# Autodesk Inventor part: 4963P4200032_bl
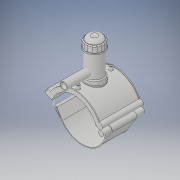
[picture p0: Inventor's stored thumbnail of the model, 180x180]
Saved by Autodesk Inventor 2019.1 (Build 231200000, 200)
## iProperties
Created: 2017-07
Part Number: 4963P4200032_bl
Material: Generic
Document SubType Name: Modeling
Designer: KIM
Density: 1 g/cm^3
Appearance: Default
Author: KIM
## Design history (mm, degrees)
derived "4963P4.ipt"
feature "Solid1::4963P4.ipt" dims "ScaleForDerivedMember" = 10
feature "Solid2::4963P4.ipt" dims "ScaleForDerivedMember" = 10
feature "Solid3::4963P4.ipt" dims "ScaleForDerivedMember" = 10
tag "TaggingFeature1"
body "Solid1"
body "Solid2"
body "Solid3"
other parameters: "d2" = 262.6 [user parameter], "d4" = 176 [user parameter], "d5" = 0 [user parameter], "d6" = 0.1 [user parameter], "d8" = 0 [user parameter], "d19" = 6 [user parameter], "d20" = 6 [user parameter], "d21" = 105.6 [user parameter], "d23" = 0 [user parameter], "d24" = 52.8 [user parameter], "d26" = 0 [user parameter], "d27" = 3 [user parameter], "d28" = 3 [user parameter], "d29" = 3 [user parameter], "d30" = 66.66667 [user parameter], "d31" = 6 [user parameter], "d32" = 0 [user parameter], "d33" = 0 [user parameter], "d34" = 0.6 [user parameter], "d40" = 120.64 [user parameter], "d43" = 0 [user parameter], "d45" = 0 [user parameter], "d47" = 221.6 [user parameter], "d70" = 15 [user parameter], "d72" = 0 [user parameter], "d73" = 6 [user parameter], "d75" = 5 [user parameter], "d76" = 0 [user parameter], "d79" = 15 [user parameter], "d80" = 70.4 [user parameter], "d82" = 5 deg [user parameter], "d84" = 4 [user parameter], "d85" = 14 [user parameter], "d86" = 0 [user parameter], "d87" = 3 [user parameter], "d88" = 0 [user parameter], "d89" = 1 [user parameter], "d90" = 1 [user parameter], "d91" = 140.8 [user parameter], "d92" = 0 [user parameter], "d93" = 0.5 [user parameter], "d94" = 105.26316 [user parameter], "d96" = 236.64 [user parameter], "d97" = 3.52 [user parameter], "d98" = 0 [user parameter], "d102" = 2 [user parameter], "d120" = 140 deg [user parameter], "d121" = 24.228 [user parameter], "d122" = 20 deg [user parameter], "d123" = 464 [user parameter], "d124" = 139.2 [user parameter], "d126" = 0 [user parameter], "d143" = 206 [user parameter], "d145" = 24.61538 [user parameter], "d149" = 3 [user parameter], "d150" = 27.07692 [user parameter], "d153" = 176 [user parameter], "d154" = 0 [user parameter], "d156" = 116 [user parameter], "d157" = 160 deg [user parameter], "d159" = 6.4 [user parameter], "d161" = 3 [user parameter], "d162" = 105.6 [user parameter], "d163" = 0 [user parameter], "d168" = 113.17073 [user parameter], "d170" = 3 [user parameter], "d172" = 0 [user parameter], "d173" = 1 [user parameter], "d176" = 20 deg [user parameter], "d177" = 14 [user parameter], "d178" = 32 [user parameter], "d180" = 0 [user parameter], "d183" = 12.8 [user parameter], "d184" = 11.2 [user parameter], "d185" = 57.2 [user parameter], "d186" = 57.2 [user parameter], "d187" = 116 [user parameter], "d188" = 9.6 [user parameter], "d189" = 14 [user parameter], "d190" = 0 [user parameter], "d191" = 174 [user parameter], "d193" = 6.4 [user parameter], "d194" = 6.16 [user parameter], "d195" = 90 deg [user parameter], "d197" = 0 [user parameter], "d199" = 0 [user parameter], "d200" = 16 [user parameter], "d202" = 0 [user parameter], "d203" = 177 [user parameter], "d204" = 76 [user parameter], "d205" = 56 [user parameter], "d206" = 68 [user parameter], "d207" = 132.75 [user parameter], "d208" = 138.06 [user parameter], "d209" = 164.61 [user parameter], "d210" = 68.8 [user parameter], "d212" = 64 [user parameter], "d213" = 36 [user parameter], "d216" = 0 [user parameter], "d219" = 4 [user parameter], "d224" = 0 [user parameter], "d225" = 56 [user parameter], "d226" = 32 [user parameter], "d227" = 25.6 [user parameter], "d228" = 132 [user parameter], "d230" = 4 [user parameter], "B_" = 202 [user parameter], "L_" = 176 [user parameter], "d_t" = 6 [user parameter], "H_2" = 177 [user parameter], "H_1" = 56 [user parameter], "d_1" = 32 [user parameter], "H_" = 132 [user parameter], "d1" = 232 [user parameter], "d148" = 3 [user parameter], "d160" = 3 [user parameter], "d169" = 3 [user parameter], "d192" = 6.4 [user parameter]
